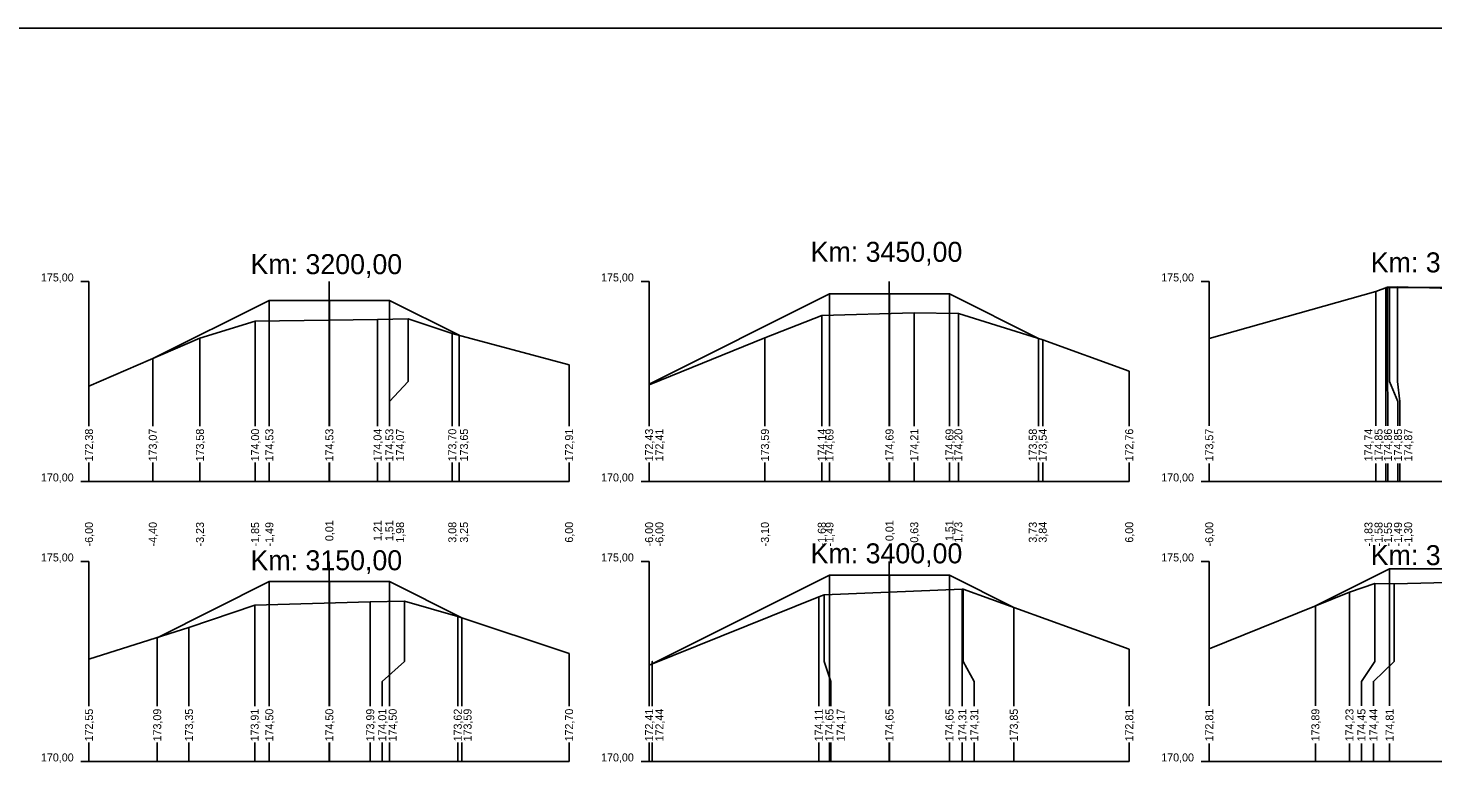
# Model space of a CAD drawing. Extents: x -614174 to -599765, y -1185887 to -1181080.
# Drawn here: x -601047.91 to -601012.8, y -1184509.31 to -1184490.94 of the extents above; entities that cross this region are included whole.
import ezdxf

# ---------------------------------------------------------------- set-up
doc = ezdxf.new("R2010")
doc.units = 0
for name, color, linetype in [('11', 7, 'Continuous'), ('16', 7, 'Continuous'), ('21', 7, 'Continuous'), ('28', 7, 'Continuous'), ('59', 7, 'Continuous'), ('8', 7, 'Continuous'), ('návrh', 7, 'Continuous')]:
    doc.layers.add(name, color=color, linetype=linetype)

msp = doc.modelspace()

# ---------------------------------------------------------------- linework, layer by layer
for points in [[(-601032.389, -1184499.837), (-601027.881, -1184497.584), (-601026.381, -1184497.584), (-601024.881, -1184497.584), (-601022.66, -1184498.694)], [(-601027.881, -1184497.584), (-601027.881, -1184497.584), (-601027.881, -1184497.584)], [(-601026.381, -1184497.584), (-601026.381, -1184497.584), (-601026.381, -1184497.584)], [(-601024.881, -1184497.584), (-601024.881, -1184497.584), (-601024.881, -1184497.584)], [(-601018.389, -1184498.698), (-601014.223, -1184497.525), (-601013.935, -1184497.41), (-601013.687, -1184497.404), (-601010.762, -1184497.497), (-601010.312, -1184497.649), (-601006.389, -1184498.857)], [(-601013.972, -1184497.424), (-601013.881, -1184497.424), (-601012.381, -1184497.424), (-601010.881, -1184497.424), (-601010.683, -1184497.524)], [(-601013.881, -1184497.424), (-601013.881, -1184497.424), (-601013.881, -1184497.424)], [(-601044.793, -1184499.199), (-601041.881, -1184497.743), (-601040.381, -1184497.743), (-601038.881, -1184497.743), (-601037.134, -1184498.616)], [(-601041.881, -1184497.743), (-601041.881, -1184497.743), (-601041.881, -1184497.743)], [(-601040.381, -1184497.743), (-601040.381, -1184497.743), (-601040.381, -1184497.743)], [(-601038.881, -1184497.743), (-601038.881, -1184497.743), (-601038.881, -1184497.743)], [(-601046.389, -1184499.889), (-601043.615, -1184498.689), (-601042.237, -1184498.266), (-601039.177, -1184498.225), (-601038.407, -1184498.204), (-601037.308, -1184498.57), (-601034.389, -1184499.355)], [(-601032.389, -1184499.858), (-601029.494, -1184498.682), (-601028.073, -1184498.125), (-601025.762, -1184498.056), (-601024.66, -1184498.068), (-601022.552, -1184498.728), (-601020.389, -1184499.514)], [(-601044.792, -1184499.198), (-601044.793, -1184499.199), (-601044.796, -1184499.2)], [(-601032.311, -1184506.83), (-601027.881, -1184504.615), (-601026.381, -1184504.615), (-601024.881, -1184504.615), (-601023.273, -1184505.419)], [(-601027.881, -1184504.615), (-601027.881, -1184504.615), (-601027.881, -1184504.615)], [(-601026.381, -1184504.615), (-601026.381, -1184504.615), (-601026.381, -1184504.615)], [(-601024.882, -1184504.615), (-601024.881, -1184504.615), (-601024.881, -1184504.615)], [(-601015.736, -1184505.384), (-601013.881, -1184504.456), (-601012.381, -1184504.456), (-601010.881, -1184504.456), (-601010.018, -1184504.888)], [(-601013.881, -1184504.456), (-601013.881, -1184504.456), (-601013.881, -1184504.456)], [(-601044.683, -1184506.176), (-601041.881, -1184504.775), (-601040.381, -1184504.775), (-601038.881, -1184504.775), (-601037.073, -1184505.679)], [(-601041.881, -1184504.775), (-601041.881, -1184504.775), (-601041.881, -1184504.775)], [(-601040.381, -1184504.775), (-601040.381, -1184504.775), (-601040.381, -1184504.775)], [(-601038.881, -1184504.775), (-601038.881, -1184504.775), (-601038.881, -1184504.775)], [(-601032.389, -1184506.862), (-601028.148, -1184505.158), (-601028.013, -1184505.103), (-601024.561, -1184504.961), (-601024.541, -1184504.961), (-601020.389, -1184506.463)], [(-601018.389, -1184506.455), (-601014.885, -1184505.04), (-601014.252, -1184504.822), (-601013.765, -1184504.83), (-601010.45, -1184504.75), (-601009.636, -1184505.01), (-601006.389, -1184506.105)], [(-601046.389, -1184506.715), (-601043.889, -1184505.924), (-601042.247, -1184505.36), (-601039.359, -1184505.279), (-601038.504, -1184505.263), (-601037.172, -1184505.646), (-601034.389, -1184506.571)], [(-601015.735, -1184505.383), (-601015.736, -1184505.384), (-601015.737, -1184505.384)], [(-601044.684, -1184506.176), (-601044.683, -1184506.176), (-601044.683, -1184506.175)], [(-601032.309, -1184506.829), (-601032.311, -1184506.83), (-601032.311, -1184506.83)]]:
    msp.add_lwpolyline(points)
at = {"layer": '11'}
for points in [[(-601027.881, -1184497.584), (-601027.881, -1184499.77), (-601027.881, -1184500.27), (-601027.881, -1184500.892)], [(-601026.381, -1184497.584), (-601026.381, -1184499.77), (-601026.381, -1184500.27), (-601026.381, -1184500.892)], [(-601024.881, -1184497.584), (-601024.881, -1184499.77), (-601024.881, -1184500.27), (-601024.881, -1184500.892)], [(-601014.223, -1184497.525), (-601014.223, -1184499.77), (-601014.223, -1184500.27), (-601014.223, -1184500.884)], [(-601013.972, -1184497.424), (-601013.972, -1184499.77), (-601013.972, -1184500.27), (-601013.972, -1184500.884)], [(-601013.935, -1184497.41), (-601013.935, -1184499.77), (-601013.923, -1184500.27), (-601013.923, -1184500.884)], [(-601013.881, -1184497.424), (-601013.881, -1184499.77), (-601013.672, -1184500.27), (-601013.672, -1184500.884)], [(-601013.687, -1184497.404), (-601013.687, -1184499.77), (-601013.623, -1184500.27), (-601013.623, -1184500.884)], [(-601041.881, -1184497.743), (-601041.881, -1184499.77), (-601041.881, -1184500.27), (-601041.881, -1184500.892)], [(-601040.381, -1184497.743), (-601040.381, -1184499.77), (-601040.381, -1184500.27), (-601040.381, -1184500.892)], [(-601038.881, -1184497.743), (-601038.881, -1184499.77), (-601038.881, -1184500.27), (-601038.881, -1184500.892)], [(-601042.237, -1184498.266), (-601042.237, -1184499.77), (-601042.237, -1184500.27), (-601042.237, -1184500.892)], [(-601039.177, -1184498.225), (-601039.177, -1184499.77), (-601039.177, -1184500.27), (-601039.177, -1184500.892)], [(-601038.407, -1184498.204), (-601038.407, -1184499.77), (-601038.877, -1184500.27), (-601038.877, -1184500.892)], [(-601028.073, -1184498.125), (-601028.073, -1184499.77), (-601028.073, -1184500.27), (-601028.073, -1184500.892)], [(-601025.762, -1184498.056), (-601025.762, -1184499.77), (-601025.762, -1184500.27), (-601025.762, -1184500.892)], [(-601024.66, -1184498.068), (-601024.66, -1184499.77), (-601024.66, -1184500.27), (-601024.66, -1184500.892)], [(-601043.615, -1184498.689), (-601043.615, -1184499.77), (-601043.615, -1184500.27), (-601043.615, -1184500.892)], [(-601037.308, -1184498.57), (-601037.308, -1184499.77), (-601037.308, -1184500.27), (-601037.308, -1184500.892)], [(-601037.134, -1184498.616), (-601037.134, -1184499.77), (-601037.134, -1184500.27), (-601037.134, -1184500.892)], [(-601029.494, -1184498.682), (-601029.494, -1184499.77), (-601029.494, -1184500.27), (-601029.494, -1184500.892)], [(-601022.66, -1184498.694), (-601022.66, -1184499.77), (-601022.66, -1184500.27), (-601022.66, -1184500.892)], [(-601018.389, -1184498.698), (-601018.389, -1184499.77), (-601018.389, -1184500.27), (-601018.389, -1184500.884)], [(-601022.552, -1184498.728), (-601022.552, -1184499.77), (-601022.552, -1184500.27), (-601022.552, -1184500.892)], [(-601044.793, -1184499.199), (-601044.793, -1184499.77), (-601044.793, -1184500.27), (-601044.793, -1184500.892)], [(-601034.389, -1184499.355), (-601034.389, -1184499.77), (-601034.389, -1184500.27), (-601034.389, -1184500.892)], [(-601046.389, -1184499.889), (-601046.389, -1184499.77), (-601046.389, -1184500.27), (-601046.389, -1184500.892)], [(-601032.389, -1184499.858), (-601032.389, -1184499.77), (-601032.389, -1184500.27), (-601032.389, -1184500.892)], [(-601032.389, -1184499.837), (-601032.389, -1184499.77), (-601032.389, -1184500.27), (-601032.389, -1184500.892)], [(-601020.389, -1184499.514), (-601020.389, -1184499.77), (-601020.389, -1184500.27), (-601020.389, -1184500.892)], [(-601046.389, -1184501.8), (-601046.389, -1184502.27)], [(-601044.793, -1184501.8), (-601044.793, -1184502.27)], [(-601043.615, -1184501.8), (-601043.615, -1184502.27)], [(-601042.237, -1184501.8), (-601042.237, -1184502.27)], [(-601041.881, -1184501.8), (-601041.881, -1184502.27)], [(-601040.381, -1184501.8), (-601040.381, -1184502.27)], [(-601039.177, -1184501.8), (-601039.177, -1184502.27)], [(-601038.881, -1184501.8), (-601038.881, -1184502.27)], [(-601038.877, -1184501.8), (-601038.877, -1184502.27)], [(-601037.308, -1184501.8), (-601037.308, -1184502.27)], [(-601037.134, -1184501.8), (-601037.134, -1184502.27)], [(-601034.389, -1184501.8), (-601034.389, -1184502.27)], [(-601032.389, -1184501.8), (-601032.389, -1184502.27)], [(-601032.389, -1184501.8), (-601032.389, -1184502.27)], [(-601029.494, -1184501.8), (-601029.494, -1184502.27)], [(-601028.073, -1184501.8), (-601028.073, -1184502.27)], [(-601027.881, -1184501.8), (-601027.881, -1184502.27)], [(-601026.381, -1184501.8), (-601026.381, -1184502.27)], [(-601025.762, -1184501.8), (-601025.762, -1184502.27)], [(-601024.881, -1184501.8), (-601024.881, -1184502.27)], [(-601024.66, -1184501.8), (-601024.66, -1184502.27)], [(-601022.66, -1184501.8), (-601022.66, -1184502.27)], [(-601022.552, -1184501.8), (-601022.552, -1184502.27)], [(-601020.389, -1184501.8), (-601020.389, -1184502.27)], [(-601018.389, -1184501.82), (-601018.389, -1184502.27)], [(-601014.223, -1184501.82), (-601014.223, -1184502.27)], [(-601013.972, -1184501.82), (-601013.972, -1184502.27)], [(-601013.923, -1184501.82), (-601013.923, -1184502.27)], [(-601013.672, -1184501.82), (-601013.672, -1184502.27)], [(-601013.623, -1184501.82), (-601013.623, -1184502.27)], [(-601027.881, -1184504.615), (-601027.881, -1184506.77), (-601027.881, -1184507.27), (-601027.881, -1184507.892)], [(-601026.381, -1184504.615), (-601026.381, -1184506.77), (-601026.381, -1184507.27), (-601026.381, -1184507.892)], [(-601024.881, -1184504.615), (-601024.881, -1184506.77), (-601024.881, -1184507.27), (-601024.881, -1184507.892)], [(-601013.881, -1184504.456), (-601013.881, -1184506.77), (-601013.881, -1184507.27), (-601013.881, -1184507.884)], [(-601041.881, -1184504.775), (-601041.881, -1184506.77), (-601041.881, -1184507.27), (-601041.881, -1184507.892)], [(-601040.381, -1184504.775), (-601040.381, -1184506.77), (-601040.381, -1184507.27), (-601040.381, -1184507.892)], [(-601038.881, -1184504.775), (-601038.881, -1184506.77), (-601038.881, -1184507.27), (-601038.881, -1184507.892)], [(-601024.561, -1184504.961), (-601024.561, -1184506.77), (-601024.561, -1184507.27), (-601024.561, -1184507.892)], [(-601024.541, -1184504.961), (-601024.541, -1184506.77), (-601024.261, -1184507.27), (-601024.261, -1184507.892)], [(-601014.885, -1184505.04), (-601014.885, -1184506.77), (-601014.885, -1184507.27), (-601014.885, -1184507.884)], [(-601014.252, -1184504.822), (-601014.252, -1184506.77), (-601014.585, -1184507.27), (-601014.585, -1184507.884)], [(-601013.765, -1184504.83), (-601013.765, -1184506.77), (-601014.285, -1184507.27), (-601014.285, -1184507.884)], [(-601042.247, -1184505.36), (-601042.247, -1184506.77), (-601042.247, -1184507.27), (-601042.247, -1184507.892)], [(-601039.359, -1184505.279), (-601039.359, -1184506.77), (-601039.359, -1184507.27), (-601039.359, -1184507.892)], [(-601038.504, -1184505.263), (-601038.504, -1184506.77), (-601039.059, -1184507.27), (-601039.059, -1184507.892)], [(-601028.148, -1184505.158), (-601028.148, -1184506.77), (-601028.148, -1184507.27), (-601028.148, -1184507.892)], [(-601028.013, -1184505.103), (-601028.013, -1184506.77), (-601027.848, -1184507.27), (-601027.848, -1184507.892)], [(-601015.736, -1184505.384), (-601015.736, -1184506.77), (-601015.736, -1184507.27), (-601015.736, -1184507.884)], [(-601037.172, -1184505.646), (-601037.172, -1184506.77), (-601037.172, -1184507.27), (-601037.172, -1184507.892)], [(-601037.073, -1184505.679), (-601037.073, -1184506.77), (-601037.073, -1184507.27), (-601037.073, -1184507.892)], [(-601023.273, -1184505.419), (-601023.273, -1184506.77), (-601023.273, -1184507.27), (-601023.273, -1184507.892)], [(-601043.889, -1184505.924), (-601043.889, -1184506.77), (-601043.889, -1184507.27), (-601043.889, -1184507.892)], [(-601044.683, -1184506.176), (-601044.683, -1184506.77), (-601044.683, -1184507.27), (-601044.683, -1184507.892)], [(-601046.389, -1184506.715), (-601046.389, -1184506.77), (-601046.389, -1184507.27), (-601046.389, -1184507.892)], [(-601034.389, -1184506.571), (-601034.389, -1184506.77), (-601034.389, -1184507.27), (-601034.389, -1184507.892)], [(-601032.389, -1184506.862), (-601032.389, -1184506.77), (-601032.389, -1184507.27), (-601032.389, -1184507.892)], [(-601032.311, -1184506.83), (-601032.311, -1184506.77), (-601032.311, -1184507.27), (-601032.311, -1184507.892)], [(-601020.389, -1184506.463), (-601020.389, -1184506.77), (-601020.389, -1184507.27), (-601020.389, -1184507.892)], [(-601018.389, -1184506.455), (-601018.389, -1184506.77), (-601018.389, -1184507.27), (-601018.389, -1184507.884)], [(-601046.389, -1184508.8), (-601046.389, -1184509.27)], [(-601044.683, -1184508.8), (-601044.683, -1184509.27)], [(-601043.889, -1184508.8), (-601043.889, -1184509.27)], [(-601042.247, -1184508.8), (-601042.247, -1184509.27)], [(-601041.881, -1184508.8), (-601041.881, -1184509.27)], [(-601040.381, -1184508.8), (-601040.381, -1184509.27)], [(-601039.359, -1184508.8), (-601039.359, -1184509.27)], [(-601039.059, -1184508.8), (-601039.059, -1184509.27)], [(-601038.881, -1184508.8), (-601038.881, -1184509.27)], [(-601037.172, -1184508.8), (-601037.172, -1184509.27)], [(-601037.073, -1184508.8), (-601037.073, -1184509.27)], [(-601034.389, -1184508.8), (-601034.389, -1184509.27)], [(-601032.389, -1184508.8), (-601032.389, -1184509.27)], [(-601032.311, -1184508.8), (-601032.311, -1184509.27)], [(-601028.148, -1184508.8), (-601028.148, -1184509.27)], [(-601027.881, -1184508.8), (-601027.881, -1184509.27)], [(-601027.848, -1184508.8), (-601027.848, -1184509.27)], [(-601026.381, -1184508.8), (-601026.381, -1184509.27)], [(-601024.881, -1184508.8), (-601024.881, -1184509.27)], [(-601024.561, -1184508.8), (-601024.561, -1184509.27)], [(-601024.261, -1184508.8), (-601024.261, -1184509.27)], [(-601023.273, -1184508.8), (-601023.273, -1184509.27)], [(-601020.389, -1184508.8), (-601020.389, -1184509.27)], [(-601018.389, -1184508.82), (-601018.389, -1184509.27)], [(-601015.736, -1184508.82), (-601015.736, -1184509.27)], [(-601014.885, -1184508.82), (-601014.885, -1184509.27)], [(-601014.585, -1184508.82), (-601014.585, -1184509.27)], [(-601014.285, -1184508.82), (-601014.285, -1184509.27)], [(-601013.881, -1184508.82), (-601013.881, -1184509.27)]]:
    msp.add_lwpolyline(points, dxfattribs=at)
at = {"layer": '16'}
for p, q in [((-601046.389, -1184502.27), (-601034.389, -1184502.27)), ((-601032.389, -1184502.27), (-601020.389, -1184502.27)), ((-601018.389, -1184502.27), (-601006.389, -1184502.27)), ((-601046.389, -1184509.27), (-601034.389, -1184509.27)), ((-601032.389, -1184509.27), (-601020.389, -1184509.27)), ((-601018.389, -1184509.27), (-601006.389, -1184509.27))]:
    msp.add_line(p, q, dxfattribs=at)
for points in [[(-601037.134, -1184498.616), (-601037.134, -1184498.616), (-601037.135, -1184498.616)], [(-601022.659, -1184498.695), (-601022.66, -1184498.694), (-601022.66, -1184498.694)], [(-601037.072, -1184505.679), (-601037.073, -1184505.679), (-601037.073, -1184505.679)], [(-601023.303, -1184505.409), (-601023.273, -1184505.419), (-601023.273, -1184505.42)]]:
    msp.add_lwpolyline(points, dxfattribs=at)
at = {"layer": '21'}
for p, q in [((-601046.589, -1184497.27), (-601046.389, -1184497.27)), ((-601032.589, -1184497.27), (-601032.389, -1184497.27)), ((-601018.589, -1184497.27), (-601018.389, -1184497.27)), ((-601046.589, -1184502.27), (-601046.389, -1184502.27)), ((-601032.589, -1184502.27), (-601032.389, -1184502.27)), ((-601018.589, -1184502.27), (-601018.389, -1184502.27)), ((-601046.589, -1184504.27), (-601046.389, -1184504.27)), ((-601032.589, -1184504.27), (-601032.389, -1184504.27)), ((-601018.589, -1184504.27), (-601018.389, -1184504.27)), ((-601046.589, -1184509.27), (-601046.389, -1184509.27)), ((-601032.589, -1184509.27), (-601032.389, -1184509.27)), ((-601018.589, -1184509.27), (-601018.389, -1184509.27))]:
    msp.add_line(p, q, dxfattribs=at)
at = {"layer": '28'}
for p, q in [((-601040.389, -1184500.892), (-601040.389, -1184497.27)), ((-601026.389, -1184500.892), (-601026.389, -1184497.27)), ((-601040.389, -1184502.27), (-601040.389, -1184501.8)), ((-601026.389, -1184502.27), (-601026.389, -1184501.8)), ((-601040.389, -1184507.892), (-601040.389, -1184504.27)), ((-601026.389, -1184507.892), (-601026.389, -1184504.27)), ((-601040.389, -1184509.27), (-601040.389, -1184508.8)), ((-601026.389, -1184509.27), (-601026.389, -1184508.8))]:
    msp.add_line(p, q, dxfattribs=at)
at = {"layer": '8'}
for p, q in [((-601046.389, -1184500.892), (-601046.389, -1184497.27)), ((-601032.389, -1184500.892), (-601032.389, -1184497.27)), ((-601018.389, -1184500.884), (-601018.389, -1184497.27)), ((-601046.389, -1184502.27), (-601046.389, -1184501.8)), ((-601032.389, -1184502.27), (-601032.389, -1184501.8)), ((-601018.389, -1184502.27), (-601018.389, -1184501.82)), ((-601046.389, -1184507.892), (-601046.389, -1184504.27)), ((-601032.389, -1184507.892), (-601032.389, -1184504.27)), ((-601018.389, -1184507.884), (-601018.389, -1184504.27)), ((-601046.389, -1184509.27), (-601046.389, -1184508.8)), ((-601032.389, -1184509.27), (-601032.389, -1184508.8)), ((-601018.389, -1184509.27), (-601018.389, -1184508.82))]:
    msp.add_line(p, q, dxfattribs=at)
at = {"layer": 'návrh'}
msp.add_line((-601090.944, -1184490.936), (-600943.944, -1184490.936), dxfattribs=at)

# ---------------------------------------------------------------- texts
msp.add_text('+', height=0.001).set_placement((-601013.973, -1184497.425))
at = {"layer": '16'}
for s, p in [('172,38', (-601046.289, -1184501.77)), ('173,07', (-601044.693, -1184501.77)), ('173,58', (-601043.515, -1184501.77)), ('174,00', (-601042.137, -1184501.77)), ('174,53', (-601041.781, -1184501.77)), ('174,53', (-601040.281, -1184501.77)), ('174,04', (-601039.077, -1184501.77)), ('174,53', (-601038.781, -1184501.77)), ('174,07', (-601038.514, -1184501.77)), ('173,70', (-601037.208, -1184501.77)), ('173,65', (-601036.916, -1184501.77)), ('172,91', (-601034.289, -1184501.77)), ('172,43', (-601032.289, -1184501.77)), ('172,41', (-601032.033, -1184501.77)), ('173,59', (-601029.394, -1184501.77)), ('174,14', (-601027.973, -1184501.77)), ('174,69', (-601027.781, -1184501.77)), ('174,69', (-601026.281, -1184501.77)), ('174,21', (-601025.662, -1184501.77)), ('174,69', (-601024.781, -1184501.77)), ('174,20', (-601024.56, -1184501.77)), ('173,58', (-601022.699, -1184501.77)), ('173,54', (-601022.452, -1184501.77)), ('172,76', (-601020.289, -1184501.77)), ('173,57', (-601018.289, -1184501.77)), ('174,74', (-601014.309, -1184501.77)), ('174,85', (-601014.058, -1184501.77)), ('174,86', (-601013.823, -1184501.77)), ('174,85', (-601013.572, -1184501.77)), ('174,87', (-601013.317, -1184501.77)), ('172,55', (-601046.289, -1184508.77)), ('173,09', (-601044.583, -1184508.77)), ('173,35', (-601043.789, -1184508.77)), ('173,91', (-601042.147, -1184508.77)), ('174,50', (-601041.781, -1184508.77)), ('174,50', (-601040.281, -1184508.77)), ('173,99', (-601039.259, -1184508.77)), ('174,01', (-601038.959, -1184508.77)), ('174,50', (-601038.698, -1184508.77)), ('173,62', (-601037.072, -1184508.77)), ('173,59', (-601036.827, -1184508.77)), ('172,70', (-601034.289, -1184508.77)), ('172,41', (-601032.289, -1184508.77)), ('172,44', (-601032.031, -1184508.77)), ('174,11', (-601028.048, -1184508.77)), ('174,65', (-601027.781, -1184508.77)), ('174,17', (-601027.499, -1184508.77)), ('174,65', (-601026.281, -1184508.77)), ('174,65', (-601024.781, -1184508.77)), ('174,31', (-601024.461, -1184508.77)), ('174,31', (-601024.161, -1184508.77)), ('173,85', (-601023.173, -1184508.77)), ('172,81', (-601020.289, -1184508.77)), ('172,81', (-601018.289, -1184508.77)), ('173,89', (-601015.636, -1184508.77)), ('174,23', (-601014.785, -1184508.77)), ('174,45', (-601014.485, -1184508.77)), ('174,44', (-601014.185, -1184508.77)), ('174,81', (-601013.781, -1184508.77))]:
    msp.add_text(s, height=0.2, rotation=90, dxfattribs=at).set_placement(p)
at = {"layer": '21'}
for s, p in [('175,00', (-601047.589, -1184497.27)), ('175,00', (-601033.589, -1184497.27)), ('175,00', (-601019.589, -1184497.27)), ('170,00', (-601047.589, -1184502.27)), ('170,00', (-601033.589, -1184502.27)), ('170,00', (-601019.589, -1184502.27)), ('175,00', (-601047.589, -1184504.27)), ('175,00', (-601033.589, -1184504.27)), ('175,00', (-601019.589, -1184504.27)), ('170,00', (-601047.589, -1184509.27)), ('170,00', (-601033.589, -1184509.27)), ('170,00', (-601019.589, -1184509.27))]:
    msp.add_text(s, height=0.2, dxfattribs=at).set_placement(p)
at = {"layer": '28'}
for s, p in [('Km: 3200,00', (-601042.352, -1184497.088)), ('Km: 3450,00', (-601028.352, -1184496.78)), ('Km: 3700,00', (-601014.352, -1184497.044)), ('Km: 3150,00', (-601042.352, -1184504.491)), ('Km: 3400,00', (-601028.352, -1184504.318)), ('Km: 3650,00', (-601014.352, -1184504.363))]:
    msp.add_text(s, height=0.5, dxfattribs=at).set_placement(p)
at = {"layer": '59'}
for s, p in [('0,01', (-601040.281, -1184503.762)), ('1,21', (-601039.077, -1184503.762)), ('1,51', (-601038.781, -1184503.762)), ('0,01', (-601026.281, -1184503.762)), ('1,51', (-601024.781, -1184503.762)), ('-6,00', (-601046.289, -1184503.893)), ('-4,40', (-601044.693, -1184503.893)), ('-3,23', (-601043.515, -1184503.894)), ('-1,85', (-601042.137, -1184503.895)), ('-1,49', (-601041.781, -1184503.894)), ('1,98', (-601038.514, -1184503.801)), ('3,08', (-601037.208, -1184503.801)), ('3,25', (-601036.916, -1184503.802)), ('6,00', (-601034.289, -1184503.8)), ('-6,00', (-601032.289, -1184503.893)), ('-6,00', (-601032.033, -1184503.893)), ('-3,10', (-601029.394, -1184503.893)), ('-1,68', (-601027.973, -1184503.894)), ('-1,49', (-601027.781, -1184503.894)), ('0,63', (-601025.662, -1184503.801)), ('1,73', (-601024.56, -1184503.801)), ('3,73', (-601022.699, -1184503.801)), ('3,84', (-601022.452, -1184503.8)), ('6,00', (-601020.289, -1184503.8)), ('-6,00', (-601018.289, -1184503.893)), ('-1,83', (-601014.309, -1184503.894)), ('-1,58', (-601014.058, -1184503.894)), ('-1,55', (-601013.823, -1184503.895)), ('-1,49', (-601013.572, -1184503.894)), ('-1,30', (-601013.317, -1184503.893))]:
    msp.add_text(s, height=0.2, rotation=90, dxfattribs=at).set_placement(p)

doc.saveas('drawing.dxf')
